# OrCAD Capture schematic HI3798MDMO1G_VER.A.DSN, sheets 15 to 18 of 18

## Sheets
15 SHEET_04: size A3
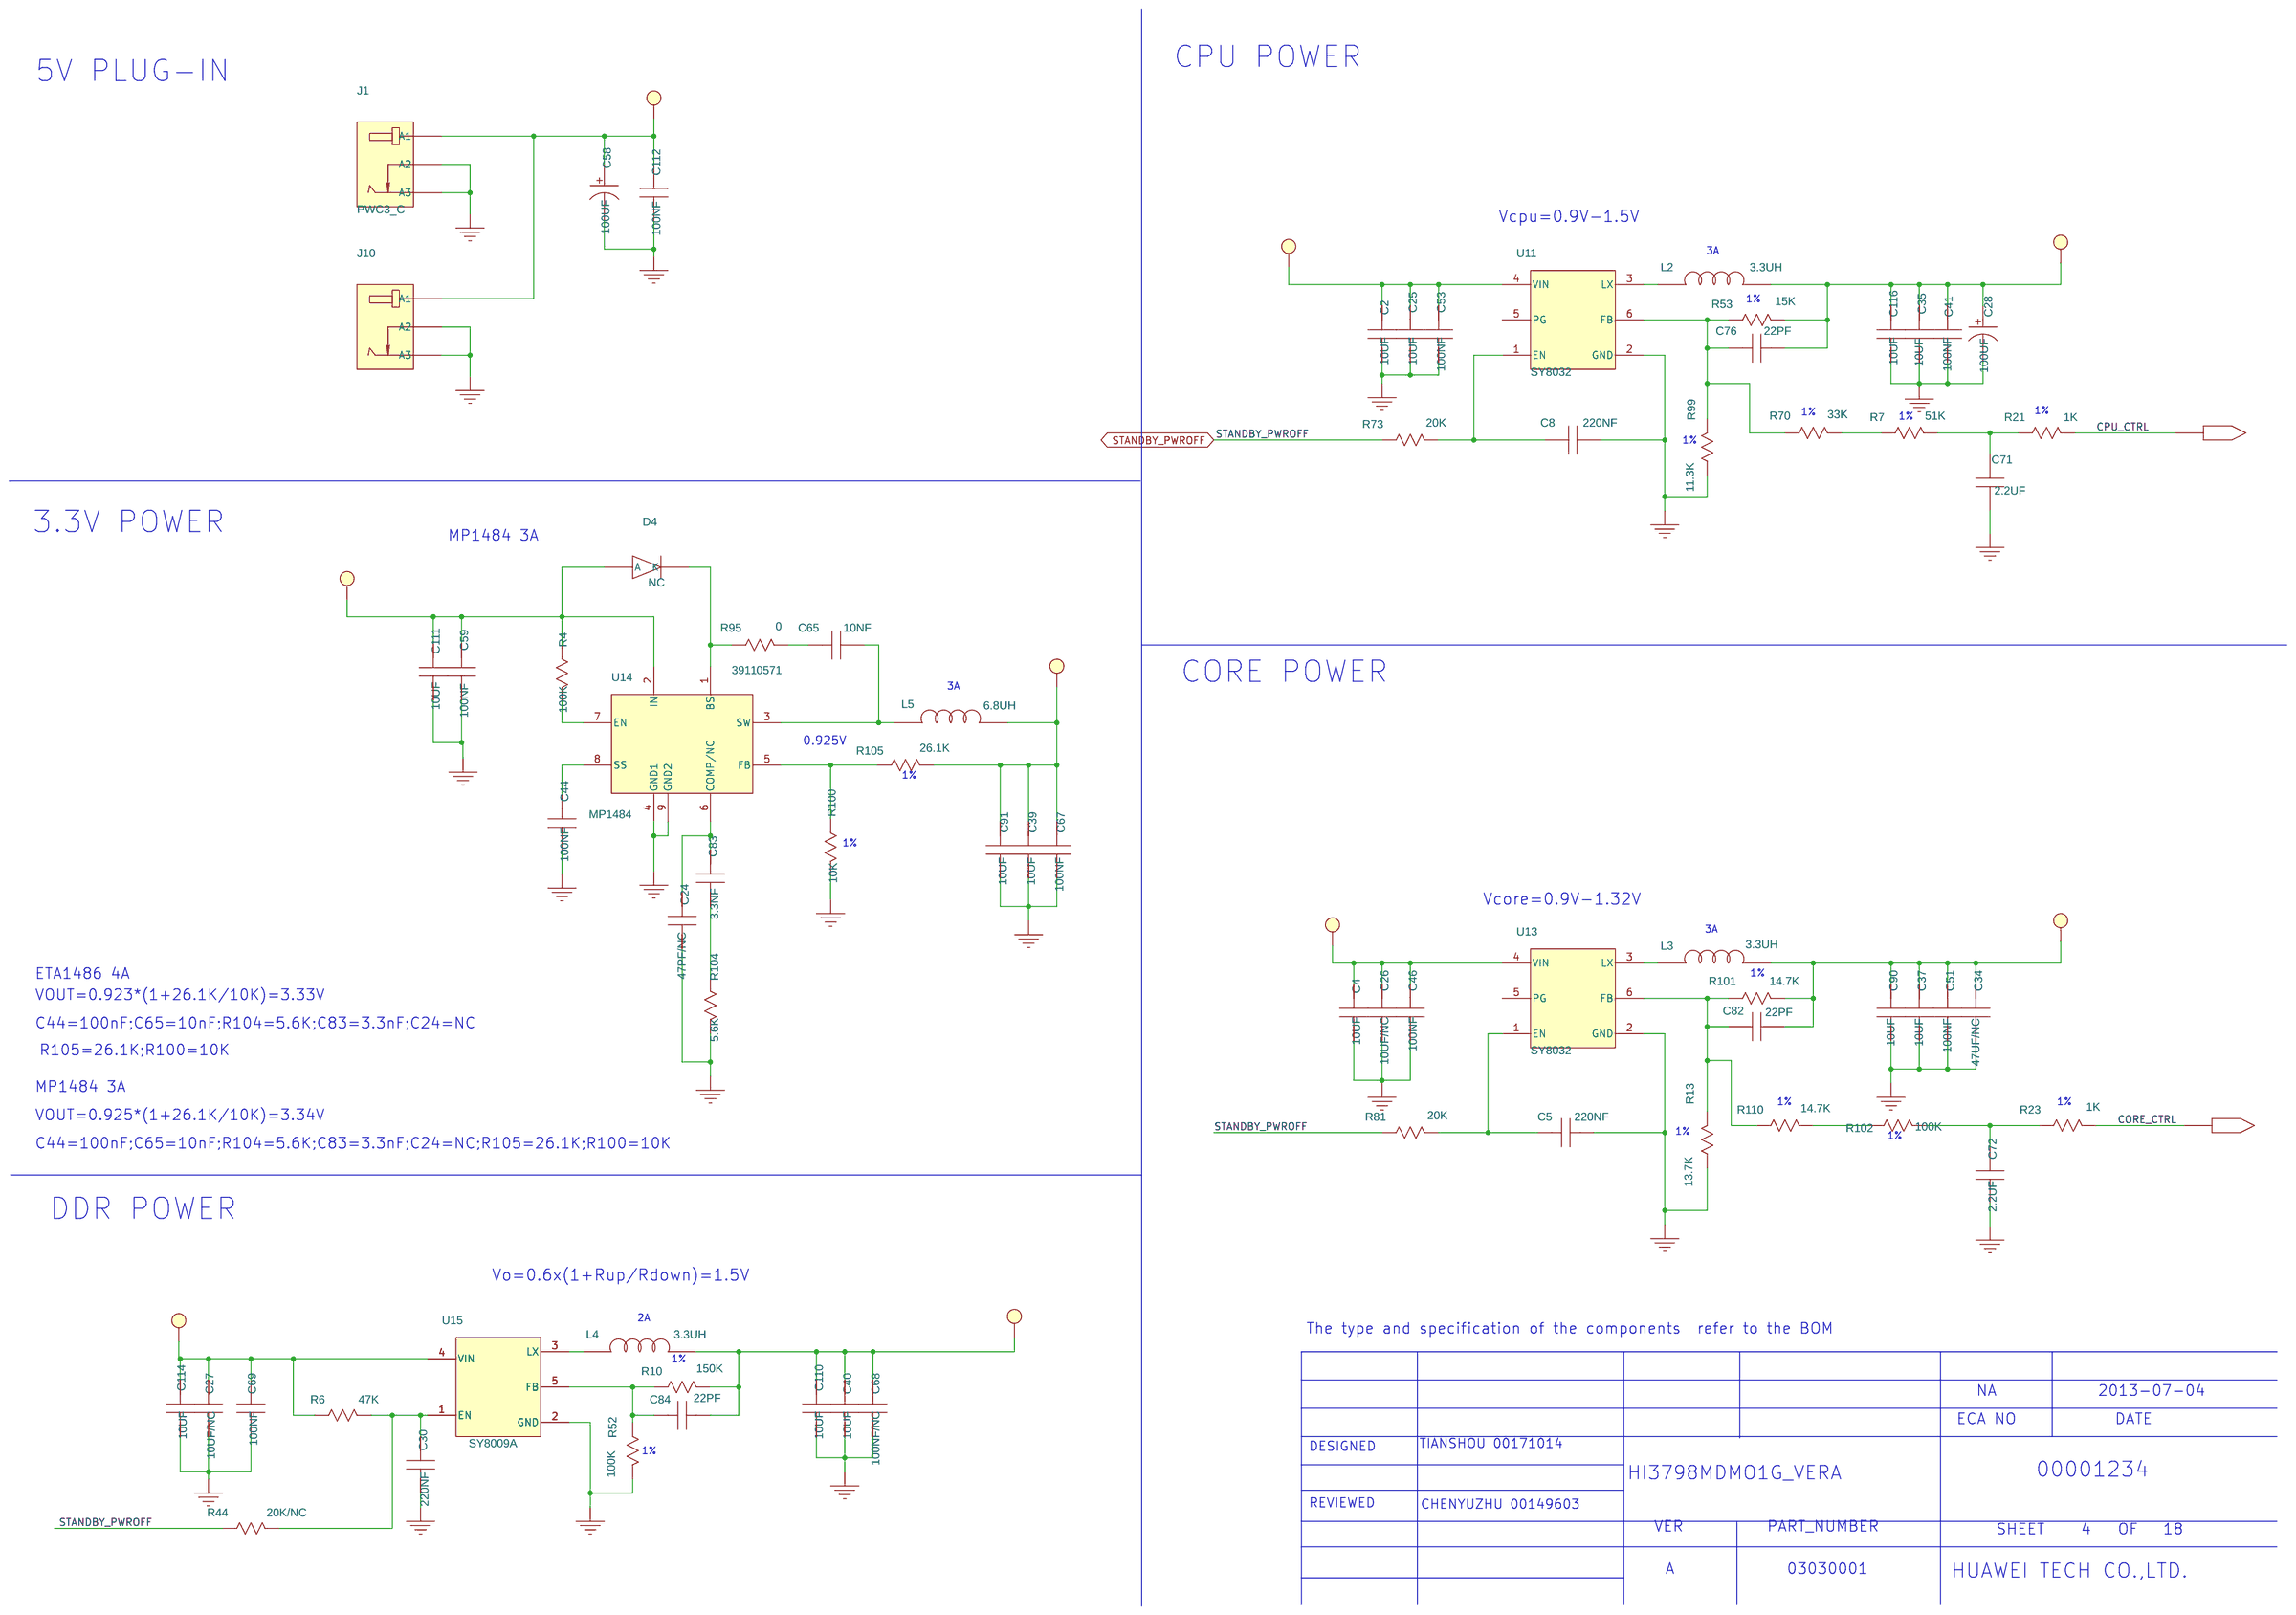
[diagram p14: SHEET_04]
16 SHEET_03: size A3
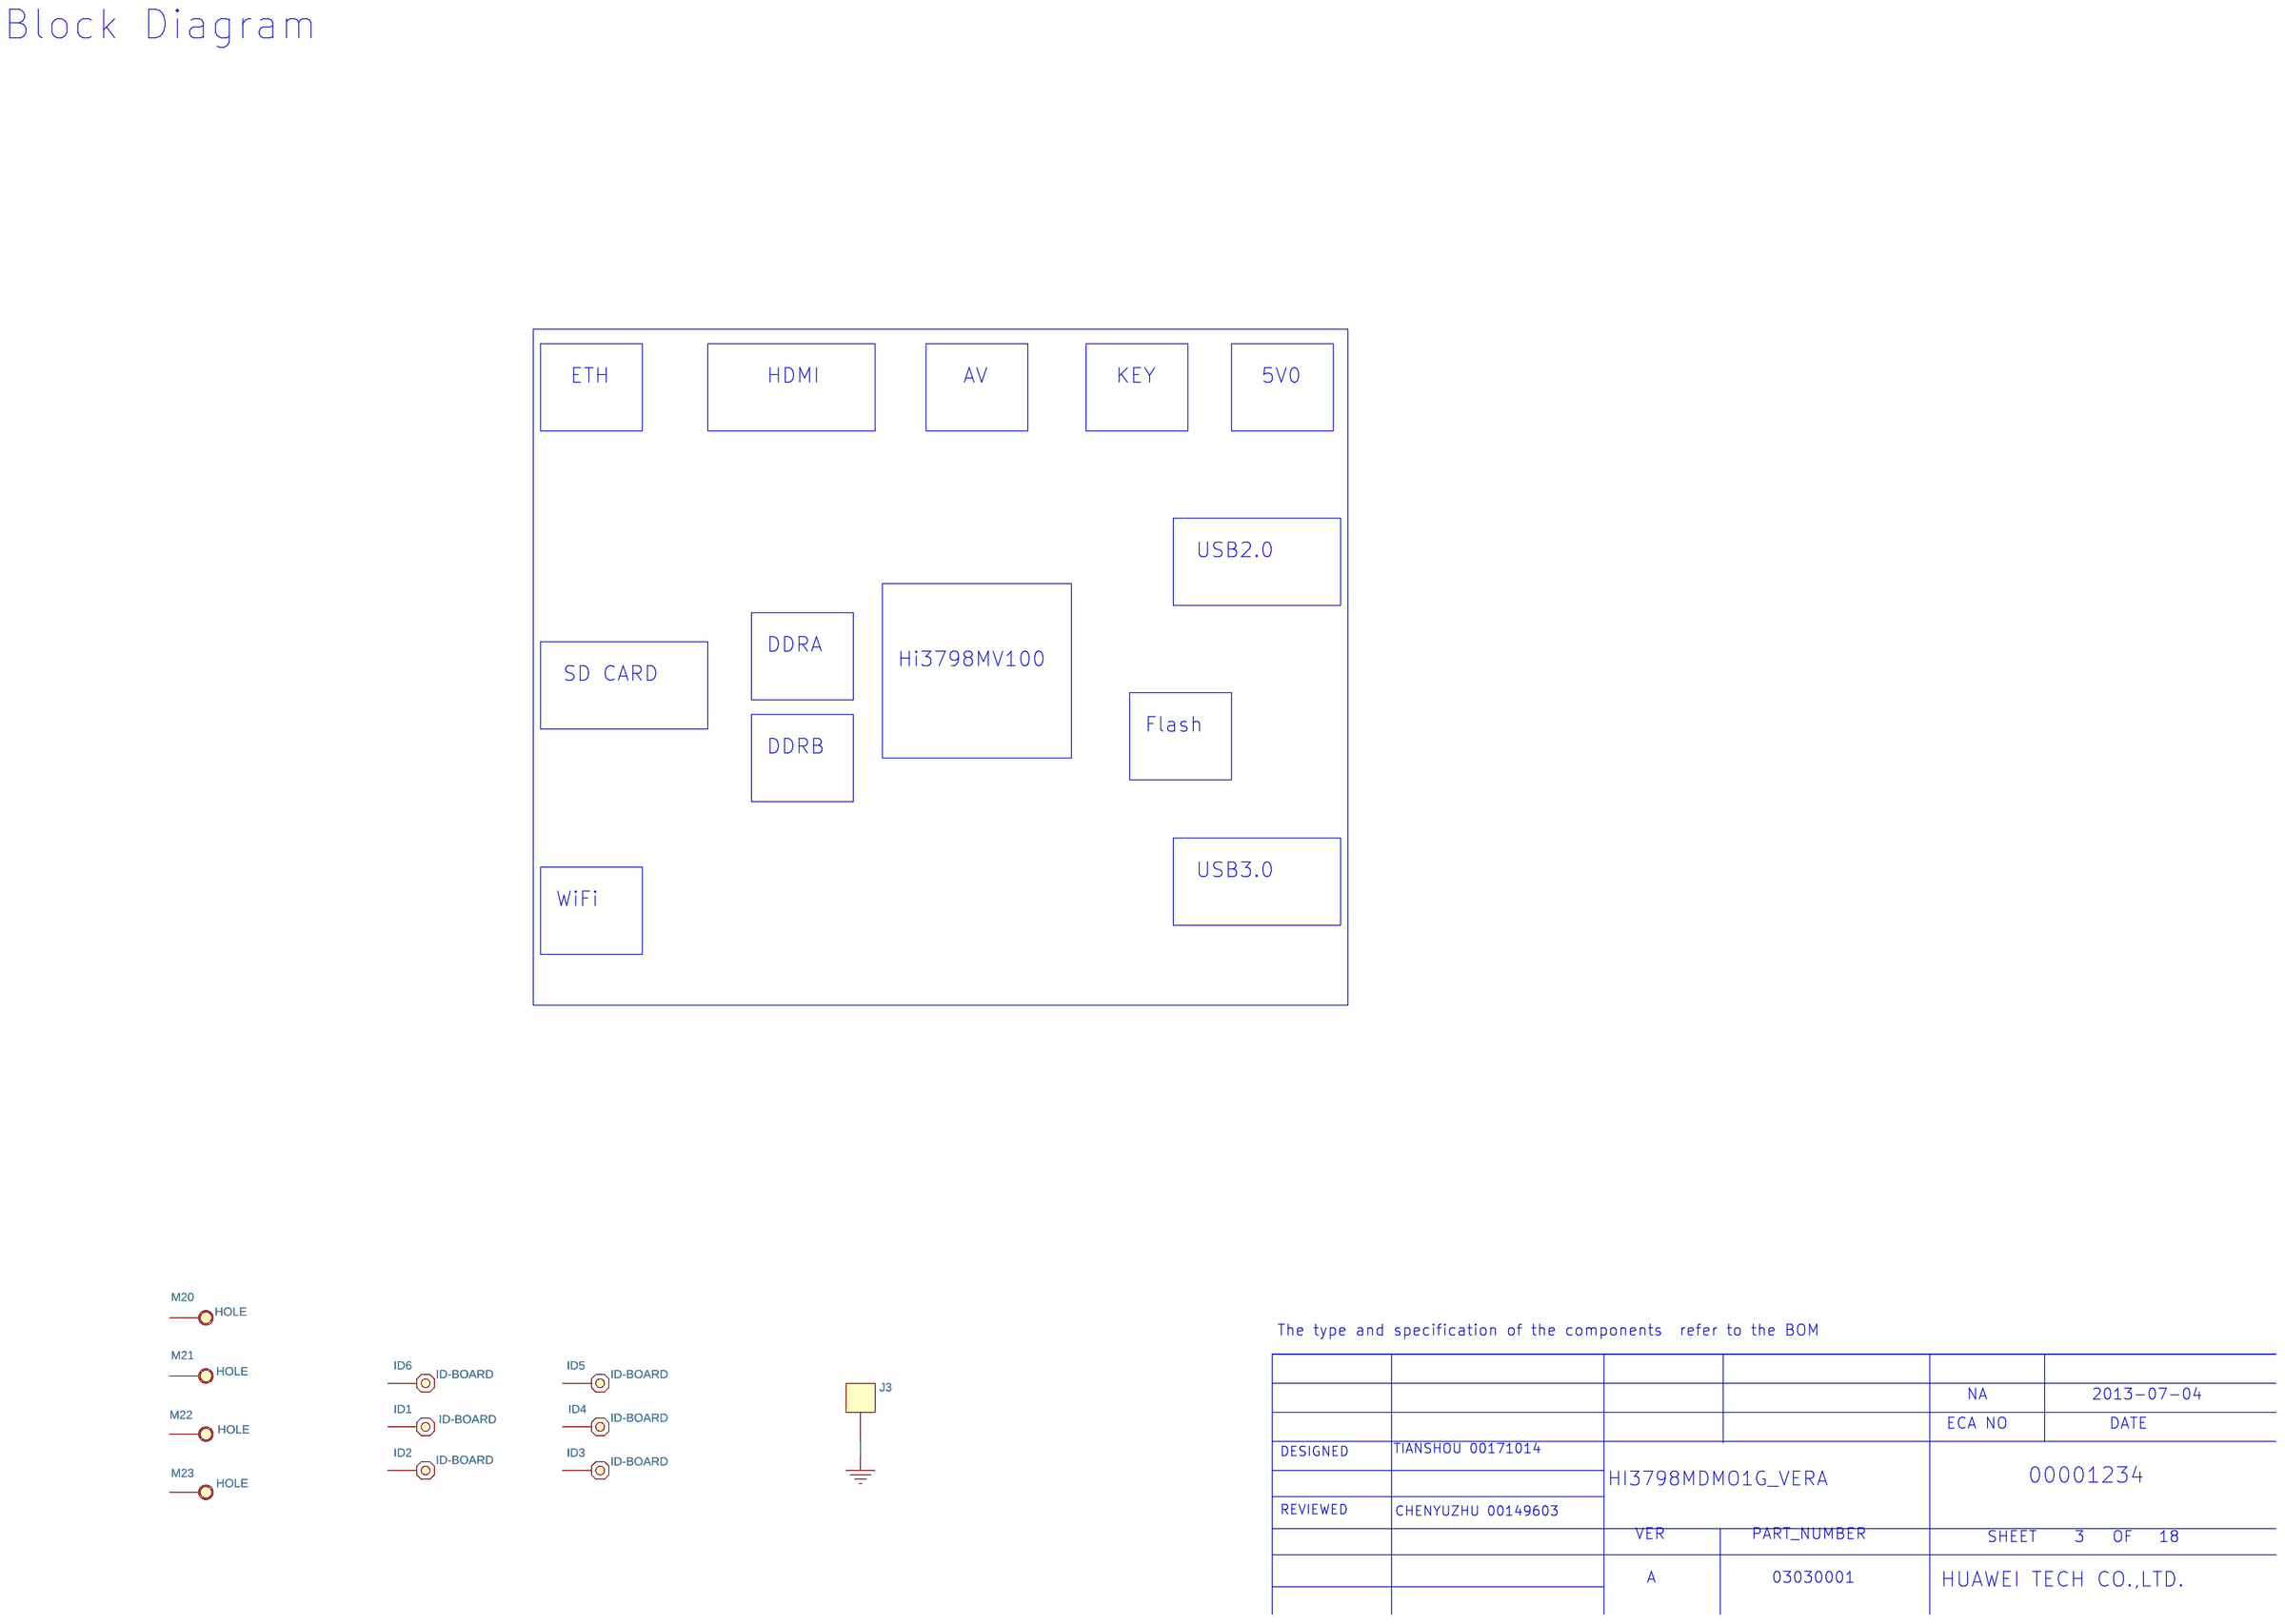
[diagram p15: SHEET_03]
17 SHEET_02
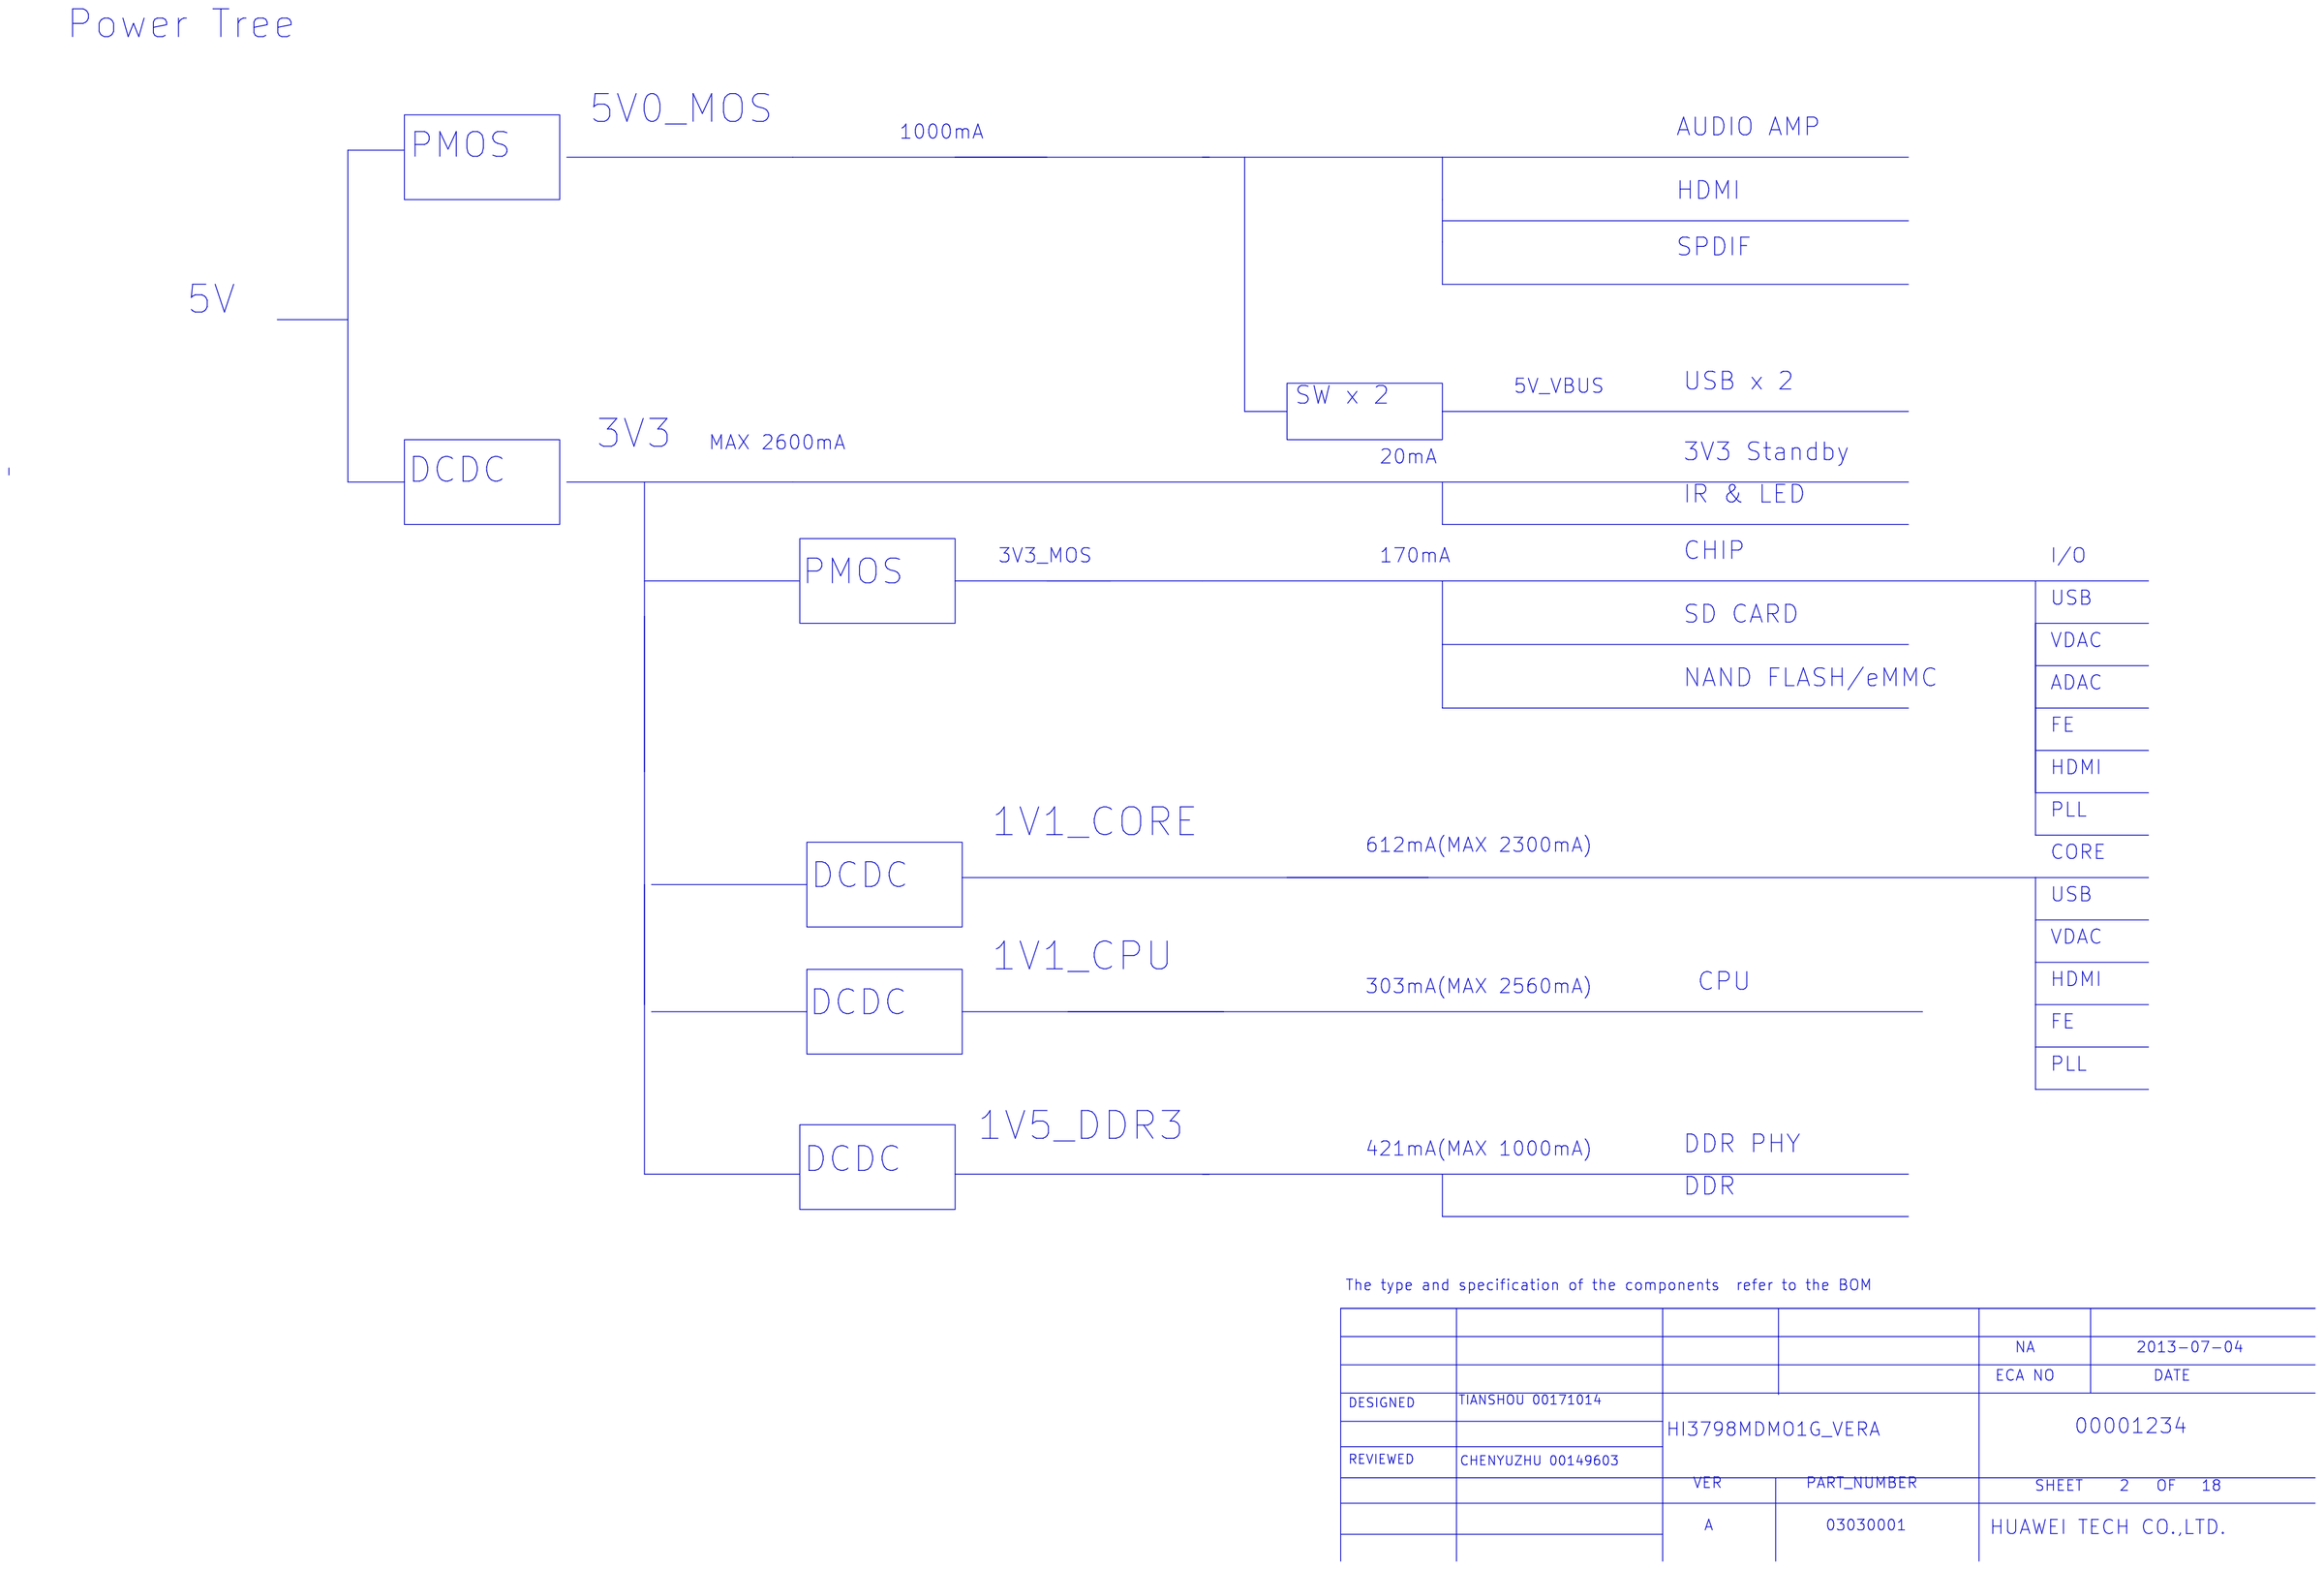
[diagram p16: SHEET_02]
18 SHEET_01
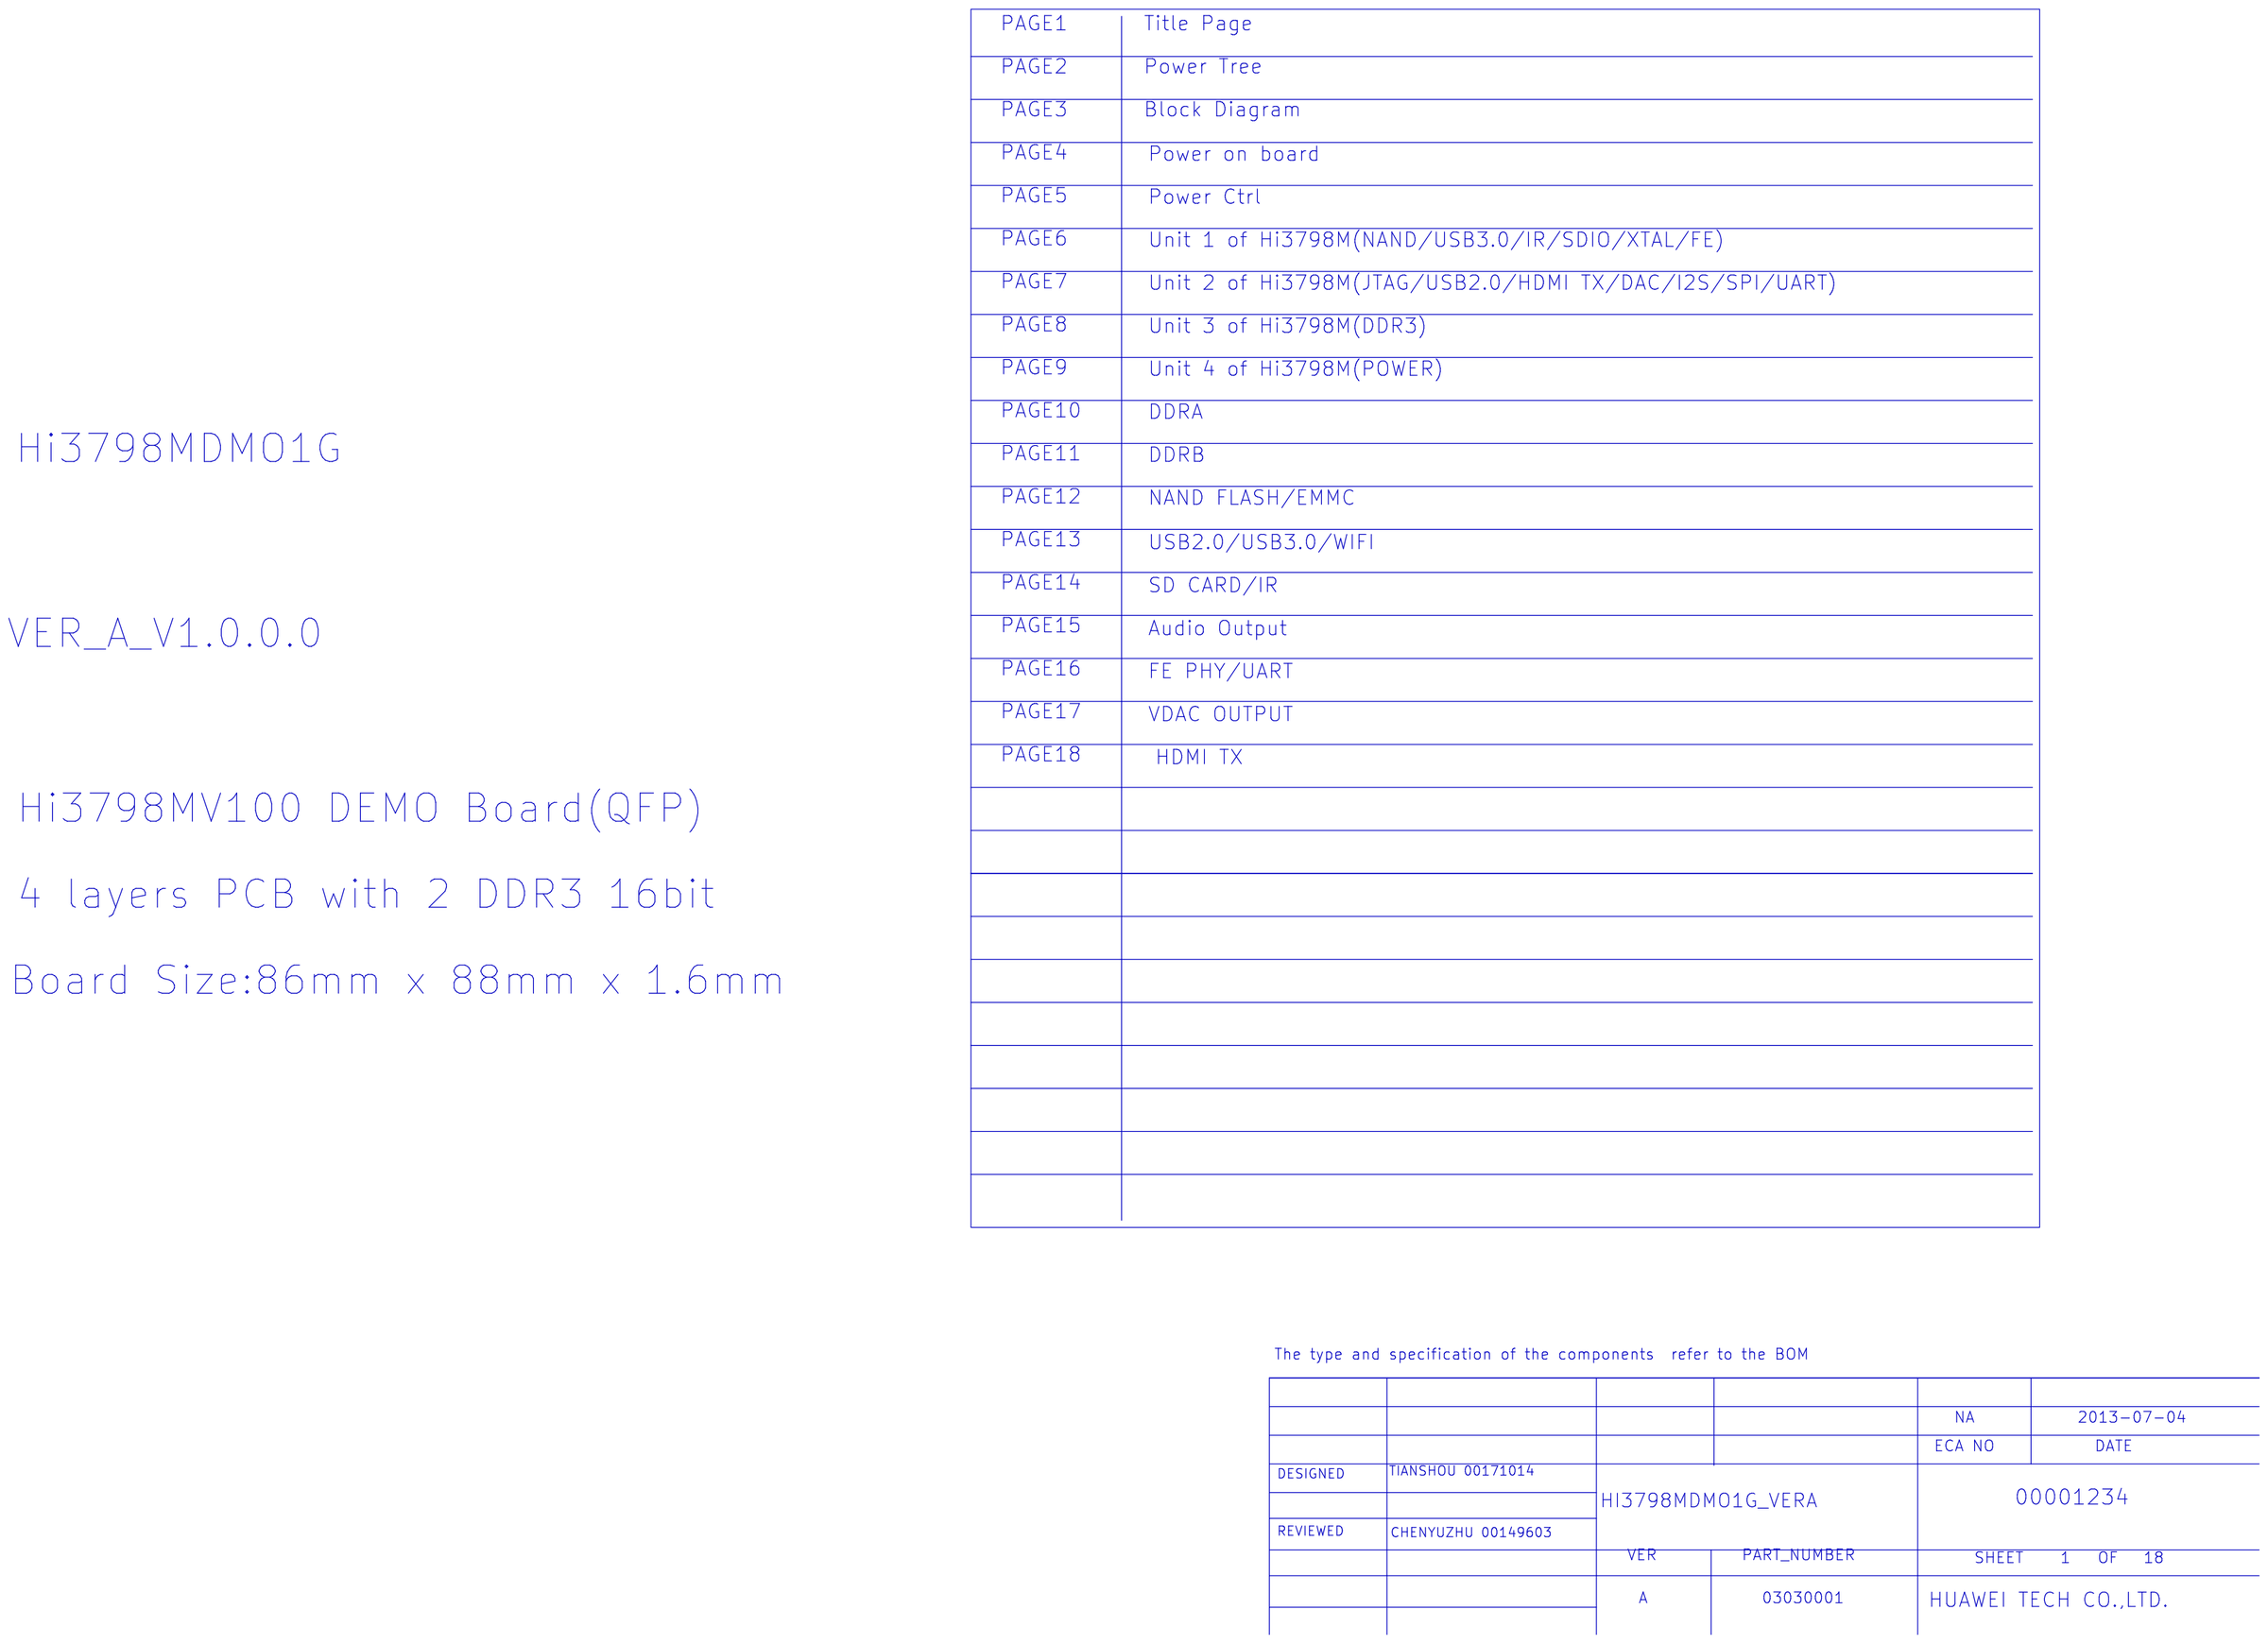
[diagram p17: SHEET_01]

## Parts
sheet SHEET_03
ID1  ID-BOARD  [ID-BOARD]
ID2  ID-BOARD  [ID-BOARD]
ID3  ID-BOARD  [ID-BOARD]
ID4  ID-BOARD  [ID-BOARD]
ID5  ID-BOARD  [ID-BOARD]
ID6  ID-BOARD  [ID-BOARD]
J3  NC  [SIP-1P]
M20  HOLE  [HOLE182-142]
M21  HOLE  [HOLE182-142]
M22  HOLE  [HOLE182-142]
M23  HOLE  [HOLE182-142]
sheet SHEET_04
C2  10UF  [SC0805]
C4  10UF  [SC0805]
C5  220NF  [SC0402]
C8  220NF  [SC0402]
C24  47PF/NC  [SC0402]
C25  10UF  [SC0805]
C26  10UF/NC  [SC0805]
C27  10UF/NC  [SC0805]
C28  100UF  [SAC6666]
C30  220NF  [SC0402]
C34  47UF/NC  [SC1206]
C35  10UF  [SC0603]
C37  10UF  [SC0603]
C39  10UF  [SC0603]
C40  10UF  [SC0603]
C41  100NF  [SC0402]
C44  100NF  [SC0402]
C46  100NF  [SC0402]
C51  100NF  [SC0402]
C53  100NF  [SC0402]
C58  100UF  [SAC6666]
C59  100NF  [SC0402]
C65  10NF  [SC0402]
C67  100NF  [SC0402]
C68  100NF/NC  [SC0402]
C69  100NF  [SC0402]
C71  2.2UF  [HSC0402]
C72  2.2UF  [HSC0402]
C76  22PF  [SC0402]
C82  22PF  [SC0402]
C83  3.3NF  [SC0402]
C84  22PF  [SC0402]
C90  10UF  [SC0603]
C91  10UF  [SC0603]
C110  10UF  [SC0603]
C111  10UF  [SC0805]
C112  100NF  [SC0402]
C114  10UF  [SC0805]
C116  10UF  [SC0603]
D4  NC  [HSOD323A]
J1  PWC3_C  [PWC3-RF-A]
J10  NC  [DC-002]
L2  3.3UH  [SWPA4020S]
L3  3.3UH  [SWPA4020S]
L4  3.3UH  [SWPA4020S]
L5  6.8UH  [SWPA5040S]
R4  100K  [SR0402]
R6  47K  [SR0402]
R7  51K  [SR0402]
R10  150K  [SR0402]
R13  13.7K  [SR0402]
R21  1K  [SR0402]
R23  1K  [SR0402]
R44  20K/NC  [SR0402]
R52  100K  [SR0402]
R53  15K  [SR0402]
R70  33K  [SR0402]
R73  20K  [SR0402]
R81  20K  [SR0402]
R95  0  [SR0402]
R99  11.3K  [SR0402]
R100  10K  [SR0402]
R101  14.7K  [SR0402]
R102  100K  [SR0402]
R104  5.6K  [SR0402]
R105  26.1K  [SR0402]
R110  14.7K  [SR0402]
U11  SY8032  [SOT23_6]
U13  SY8032  [SOT23_6]
U14  MP1484  [SOIC8N]
U15  SY8009A  [SOT23_5]

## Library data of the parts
ID1-ID6 = ID-BOARD: %195%%232%%202%%246%: PCB-MARK点ID-BOARD，亮铜直径40MIL，阻焊开窗直径80MIL，MARK点大小120MIL。; DEVICE: PCB_MARKPOINT_A
J3 = SIP1: %195%%232%%202%%246%: 插针-普通方脚插针-1PIN-单排-直式-5.84MM-2.92MM-2.54MM-THT; %208%%161%%192%%224%%195%%251%%179%%198%: 插针; CODE: 14050101; DEVICE: TSW_101_23_F_S
M20-M23 = HOLE: %195%%232%%202%%246%: 自建封装; DEVICE: M3_HOLE_A
C2 C4 C25-C27 C111 C114 = C: %182%%238%%182%%168%%185%%164%%215%%247%%181%%231%%209%%185%(V): 25; %195%%232%%202%%246%: SMD陶瓷电容-25V-10000NF-+/-20%-X5R-0805; %208%%161%%192%%224%%195%%251%%179%%198%: SMD陶瓷电容; CODE: 8071629; COMPONENT_HIGH_MAX: 1.45MM; DEVICE: C2012X5R1E106KT000N1
C5 C8 C30 = C: %182%%238%%182%%168%%185%%164%%215%%247%%181%%231%%209%%185%(V): 6.3; %195%%232%%202%%246%: SMD陶瓷电容-6.3V-220NF-+/-10%-X5R-0402-BT; %208%%161%%192%%224%%195%%251%%179%%198%: SMD陶瓷电容; CODE: 8070584; COMPONENT_HIGH_MAX: 0.55MM; DEVICE: GRM155R60J224KE01D
C24 = C: %182%%238%%182%%168%%185%%164%%215%%247%%181%%231%%209%%185%(V): 50; %195%%232%%202%%246%: SMD陶瓷电容-50V-0.047NF-±5%-NP0-0402; %208%%161%%192%%224%%195%%251%%179%%198%: SMD陶瓷电容; CODE: 8070549; COMPONENT_HIGH_MAX: 0.55MM; DEVICE: C0402C470J5GAC_7867
C28 C58 = CP: %182%%238%%182%%168%%185%%164%%215%%247%%181%%231%%209%%185%(V): 16; %195%%232%%202%%246%: 非固体SMD铝电容-16V-100UF-+/-20%-6.3*5.4MM-极性-105DEGC-1000H-片式,温度敏感器件-工艺耐温250DEGC,5S; %208%%161%%192%%224%%195%%251%%179%%198%: 非固体SMD铝电容; CODE: 8010269; COMPONENT_HIGH_MAX: 5.7MM; DEVICE: UWT1C101MCL1GB
C34 = C: %182%%238%%182%%168%%185%%164%%215%%247%%181%%231%%209%%185%(V): 6.3; %195%%232%%202%%246%: SMD陶瓷电容-6.3V-47000NF-+/-20%-X5R-1206; %208%%161%%192%%224%%195%%251%%179%%198%: SMD陶瓷电容; CODE: 8070680; COMPONENT_HIGH_MAX: 1.9MM; DEVICE: CM316X5R476M06AT
C35 C37 C39 C40 C90 C91 C110 C116 = C: %182%%238%%182%%168%%185%%164%%215%%247%%181%%231%%209%%185%(V): 6.3; %195%%232%%202%%246%: SMD陶瓷电容-6.3V-10000NF-+/-20%-X5R-0603-BT,TS16949; %208%%161%%192%%224%%195%%251%%179%%198%: SMD陶瓷电容; CODE: 8070649; COMPONENT_HIGH_MAX: 0.9MM; DEVICE: C1608X5R0J106MT0A0E
C41 C44 C46 C51 C53 C59 C67-C69 C112 = C: %182%%238%%182%%168%%185%%164%%215%%247%%181%%231%%209%%185%(V): 16; %195%%232%%202%%246%: SMD陶瓷电容-16V-100NF-±10%-X7R-0402; %208%%161%%192%%224%%195%%251%%179%%198%: SMD陶瓷电容; CODE: 8070614; COMPONENT_HIGH_MAX: 0.6MM; DEVICE: RMEMK105BJ104KV_FR
C65 = C: %182%%238%%182%%168%%185%%164%%215%%247%%181%%231%%209%%185%(V): 16; %195%%232%%202%%246%: SMD陶瓷电容-16V-10NF-+/-10%-X7R-0402-BT,TS16949; %208%%161%%192%%224%%195%%251%%179%%198%: SMD陶瓷电容; CODE: 8070449; COMPONENT_HIGH_MAX: 0.55MM; DEVICE: GRM155R71C103KA01D
C71 C72 = C: %182%%238%%182%%168%%185%%164%%215%%247%%181%%231%%209%%185%(V): 6.3; %195%%232%%202%%246%: SMD陶瓷电容-6.3V-2200NF-+/-20%-X5R-0402-TS16949; %208%%161%%192%%224%%195%%251%%179%%198%: SMD陶瓷电容; CODE: 8070667; COMPONENT_HIGH_MAX: 0.6MM; DEVICE: GRM155R60J225ME15D
C76 C82 C84 = C: %182%%238%%182%%168%%185%%164%%215%%247%%181%%231%%209%%185%(V): 50; %195%%232%%202%%246%: SMD陶瓷电容-50V-0.022NF-+/-5%-NP0-0402-BT; %208%%161%%192%%224%%195%%251%%179%%198%: SMD陶瓷电容; CODE: 8070545; COMPONENT_HIGH_MAX: 0.55MM; DEVICE: RMUMK105CG220JV_F
C83 = C: %182%%238%%182%%168%%185%%164%%215%%247%%181%%231%%209%%185%(V): 50; %195%%232%%202%%246%: SMD陶瓷电容-50V-3.3NF-±10%-X7R-0402; %208%%161%%192%%224%%195%%251%%179%%198%: SMD陶瓷电容; CODE: 8070621; COMPONENT_HIGH_MAX: 0.55MM; DEVICE: GRM155R71H332KA01D
D4 = D_A: %195%%232%%202%%246%: 肖特基二极管-10V-3A-0.24V-SOD323-BT; %208%%161%%192%%224%%195%%251%%179%%198%: 肖特基二极管; CODE: 15010252; COMPONENT_HIGH_MAX: 1.1MM; DEVICE: IN4148
J1 = PWC3_C: %195%%232%%202%%246%: IO连接器-DC JACK-3PIN-母座-3.9/1.3MM弯式-5V2A-00482858; CODE: 14240410; COMPONENT_HIGH_MAX: 11.25MM; DEVICE: DC_012_HW
J10 = PWC3_C: %195%%232%%202%%246%: IO连接器-DC JACK-3PIN-母座-3.9/1.3MM弯式-5V2A-00482858; CODE: *; COMPONENT_HIGH_MAX: 11.25MM; DEVICE: DC_012_HW
L2-L4 = SWPA4020S3R3MT
L5 = SWPA5040S6R8MT
R4 = R: %182%%238%%182%%168%%185%%166%%194%%202%(W): 0.06; %195%%232%%202%%246%: 片式厚膜电阻器-0.0625W-100000OHM-+/-5%-0402; %208%%161%%192%%224%%195%%251%%179%%198%: 片式厚膜电阻器; %215%%232%%214%%181%%212%%202%%208%%237%%198%%171%%178%%238%: +/-5%; CODE: 7090831; COMPONENT_HIGH_MAX: 0.4MM; DEVICE: RK73B1ELTP104J
R6 = R: %182%%238%%182%%168%%185%%166%%194%%202%(W): 0.06; %195%%232%%202%%246%: 片式厚膜电阻器-0.0625W-47000OHM-+/-5%-0402-ELOM; %208%%161%%192%%224%%195%%251%%179%%198%: 片式厚膜电阻器; %215%%232%%214%%181%%212%%202%%208%%237%%198%%171%%178%%238%: +/-5%; CODE: 7090819; COMPONENT_HIGH_MAX: 0.4MM; DEVICE: RC0402JR_0747K
R7 R100 = R: %182%%238%%182%%168%%185%%166%%194%%202%(W): 0.06; %195%%232%%202%%246%: 片式厚膜电阻器-0.0625W-10000OHM-+/-1%-0402-BT; %208%%161%%192%%224%%195%%251%%179%%198%: 片式厚膜电阻器; %215%%232%%214%%181%%212%%202%%208%%237%%198%%171%%178%%238%: +/-1%; CODE: 7090867; COMPONENT_HIGH_MAX: 0.4MM; DEVICE: RK73H1ETTP1002F
R10 = R: %182%%238%%182%%168%%185%%166%%194%%202%(W): 0.06; %195%%232%%202%%246%: 片式厚膜电阻器-0.0625W-150000OHM-+/-1%-0402; %208%%161%%192%%224%%195%%251%%179%%198%: 片式厚膜电阻器; %215%%232%%214%%181%%212%%202%%208%%237%%198%%171%%178%%238%: +/-1%; CODE: 7090833; COMPONENT_HIGH_MAX: 0.4MM; DEVICE: RK73H1ELTP1503F
R13 = R: %182%%238%%182%%168%%185%%166%%194%%202%(W): 0.06; %195%%232%%202%%246%: 片式厚膜电阻器-0.0625W-13700OHM-+/- 1%-0402-供电专用-供电专用; %208%%161%%192%%224%%195%%251%%179%%198%: 片式厚膜电阻器; %215%%232%%214%%181%%212%%202%%208%%237%%198%%171%%178%%238%: +/- 1%; CODE: 7091435; COMPONENT_HIGH_MAX: 0.4MM; DEVICE: RC0402FR_0713K7L
R21 R23 = R: %182%%238%%182%%168%%185%%166%%194%%202%(W): 0.1; %195%%232%%202%%246%: 片式厚膜电阻器-0.1W-1000OHM-+/-1%-0603; %208%%161%%192%%224%%195%%251%%179%%198%: 片式厚膜电阻器; %215%%232%%214%%181%%212%%202%%208%%237%%198%%171%%178%%238%: +/-1%; CODE: 7092250; COMPONENT_HIGH_MAX: 0.5MM; DEVICE: RK73H1JTTD1001F
R44 R73 R81 = R: %182%%238%%182%%168%%185%%166%%194%%202%(W): 0.06; %195%%232%%202%%246%: 片式厚膜电阻器-0.0625W-20000OHM-+/-1%-0402-TS16949; %208%%161%%192%%224%%195%%251%%179%%198%: 片式厚膜电阻器; %215%%232%%214%%181%%212%%202%%208%%237%%198%%171%%178%%238%: +/-1%; CODE: 7091374; COMPONENT_HIGH_MAX: 0.4MM; DEVICE: RC_02W2002FT
R52 = R: %182%%238%%182%%168%%185%%166%%194%%202%(W): 0.06; %195%%232%%202%%246%: 片式厚膜电阻器-0.0625W-100000OHM-+/-5%-0402-BT; %208%%161%%192%%224%%195%%251%%179%%198%: 片式厚膜电阻器; %215%%232%%214%%181%%212%%202%%208%%237%%198%%171%%178%%238%: +/-5%; CODE: 7090831; COMPONENT_HIGH_MAX: 0.4MM; DEVICE: RK73B1ELTP104J
R53 = R: %182%%238%%182%%168%%185%%166%%194%%202%(W): 0.06; %195%%232%%202%%246%: 片式厚膜电阻器-0.0625W-13000OHM-+/-1%-0402-BT; %208%%161%%192%%224%%195%%251%%179%%198%: 片式厚膜电阻器; %215%%232%%214%%181%%212%%202%%208%%237%%198%%171%%178%%238%: +/-1%; CODE: *; COMPONENT_HIGH_MAX: 0.4MM; DEVICE: RC_02W1502FT
R70 = R: %182%%238%%182%%168%%185%%166%%194%%202%(W): 0.06; %195%%232%%202%%246%: 片式厚膜电阻器-0.0625W-75000OHM-+/-1%-0402; %208%%161%%192%%224%%195%%251%%179%%198%: 片式厚膜电阻器; %215%%232%%214%%181%%212%%202%%208%%237%%198%%171%%178%%238%: +/-1%; CODE: 7091008; COMPONENT_HIGH_MAX: 0.4MM; DEVICE: RK73H1ETTD7502F
R95 = R: %182%%238%%182%%168%%185%%166%%194%%202%(W): 0.06; %195%%232%%202%%246%: 片式厚膜电阻器-0.0625W-0OHM-< 50MOHM-0402-1A-BT; %208%%161%%192%%224%%195%%251%%179%%198%: 片式厚膜电阻器; %215%%232%%214%%181%%212%%202%%208%%237%%198%%171%%178%%238%: < 50MOHM; CODE: 7090800; DEVICE: RC0402JR_070R
R99 = R: %182%%238%%182%%168%%185%%166%%194%%202%(W): 0.06; %195%%232%%202%%246%: 片式厚膜电阻器-0.0625W-11000OHM-+/-1%-0402-BT; %208%%161%%192%%224%%195%%251%%179%%198%: 片式厚膜电阻器; %215%%232%%214%%181%%212%%202%%208%%237%%198%%171%%178%%238%: +/-1%; CODE: 7091271; COMPONENT_HIGH_MAX: 0.4MM; DEVICE: RK73H1ETTP1102F
R101 R110 = R: %182%%238%%182%%168%%185%%166%%194%%202%(W): 0.06; %195%%232%%202%%246%: 片式厚膜电阻器-0.0625W-14700OHM-+/-1%-0402; %208%%161%%192%%224%%195%%251%%179%%198%: 片式厚膜电阻器; %215%%232%%214%%181%%212%%202%%208%%237%%198%%171%%178%%238%: +/-1%; CODE: *; COMPONENT_HIGH_MAX: 0.4MM; DEVICE: RK73H1ETTD7502F
R102 = R: %182%%238%%182%%168%%185%%166%%194%%202%(W): 0.06; %195%%232%%202%%246%: 片式厚膜电阻器-0.0625W-100000OHM-+/-1%-0402; %208%%161%%192%%224%%195%%251%%179%%198%: 片式厚膜电阻器; %215%%232%%214%%181%%212%%202%%208%%237%%198%%171%%178%%238%: +/-1%; CODE: 7090875; COMPONENT_HIGH_MAX: 0.4MM; DEVICE: RK73H1ETTP1003F
R104 = R: %182%%238%%182%%168%%185%%166%%194%%202%(W): 0.06; %195%%232%%202%%246%: 片式厚膜电阻器-0.0625W-5600OHM-+/-1%-0402-BT; %208%%161%%192%%224%%195%%251%%179%%198%: 片式厚膜电阻器; %215%%232%%214%%181%%212%%202%%208%%237%%198%%171%%178%%238%: +/-1%; CODE: 7091275; COMPONENT_HIGH_MAX: 0.4MM; DEVICE: RK73H1ETTP5601F
R105 = R: %182%%238%%182%%168%%185%%166%%194%%202%(W): 0.06; %195%%232%%202%%246%: 片式厚膜电阻器-0.0625W-26100OHM-+/-1%-0402; %208%%161%%192%%224%%195%%251%%179%%198%: 片式厚膜电阻器; %215%%232%%214%%181%%212%%202%%208%%237%%198%%171%%178%%238%: +/-5%; CODE: *; COMPONENT_HIGH_MAX: 0.4MM; DEVICE: RK73B1ETTP273J
U11 U13 = SY8032
U14 = MP1484: CODE: 39110571
U15 = SY8009A

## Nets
1V1_CORE: C34.1(A) C37.1(A) C51.1(A) C82.2(B) C90.1(A) L3.2(B) R101.2(B) ; also on sheet 10 12 13
1V1_CPU: C28.1 C35.1(A) C41.1(A) C76.2(B) C116.1(A) L2.2(B) R53.2(B) ; also on sheet 10
1V5_DDR3: C40.1(A) C68.1(A) C84.2(B) C110.1(A) L4.2(B) R10.2(B) ; also on sheet 8 9 11
3V3: C2.1(A) C4.1(A) C25.1(A) C26.1(A) C27.1(A) C39.1(A) C46.1(A) C53.1(A) C67.1(A) C69.1(A) C91.1(A) C114.1(A) L5.2(B) R6.1(A) R105.2(B) U11.4(VIN) U13.4(VIN) U15.4(VIN) ; also on sheet 3 5 10 13 14
5V0: C58.1 C59.1(A) C111.1(A) C112.1(A) D4.2(A) J1.1(A1) J10.1(A1) R4.1(A) U14.2(IN) ; also on sheet 14
GND: C2.2(B) C4.2(B) C5.2(B) C8.2(B) C24.2(B) C25.2(B) C26.2(B) C27.2(B) C28.2 C30.2(B) C34.2(B) C35.2(B) C37.2(B) C39.2(B) C40.2(B) C41.2(B) C44.2(B) C46.2(B) C51.2(B) C53.2(B) C58.2 C59.2(B) C67.2(B) C68.2(B) C69.2(B) C71.2(B) C72.2(B) C90.2(B) C91.2(B) C110.2(B) C111.2(B) C112.2(B) C114.2(B) C116.2(B) J1.2(A2) J1.3(A3) J3.1 J10.2(A2) J10.3(A3) R13.1(A) R52.2(B) R99.1(A) R100.2(B) R104.2(B) U11.2(GND) U13.2(GND) U14.4(GND1) U14.9(GND2) U15.2(GND) ; also on sheet 1 2 3 4 5 6 7 8 9 10 11 12 13 14
CORE_CTRL: R23.2(B) ; also on sheet 12
CPU_CTRL: R21.2(B) ; also on sheet 12
STANDBY_PWROFF: R44.1(A) R73.1(A) R81.1(A) ; also on sheet 13 14
N3785646: C71.1(A) R7.2(B) R21.1(A)
N3786188: C82.1(A) R13.2(B) R101.1(A) R110.1(A) U13.6(FB)
N3786224: C5.1(A) R81.2(B) U13.1(EN)
N3786240: C65.2(B) L5.1(A) U14.3(SW)
N3786256: C44.1(A) U14.8(SS)
N3786340: C76.1(A) R53.1(A) R70.1(A) R99.2(B) U11.6(FB)
N3786376: C8.1(A) R73.2(B) U11.1(EN)
N3786392: L4.1(A) U15.3(LX)
N3786396: C84.1(A) R10.1(A) R52.1(A) U15.5(FB)
N3786468: L3.1(A) U13.3(LX)
N3786472: R102.1(A) R110.2(B)
N3786476: L2.1(A) U11.3(LX)
N3786480: C65.1(A) R95.2(B)
N3786484: R4.2(B) U14.7(EN)
N3786492: C24.1(A) C83.1(A) U14.6(COMP/NC)
N3786508: C83.2(B) R104.1(A)
N3786512: D4.1(K) R95.1(A) U14.1(BS)
N3786528: R100.1(A) R105.1(A) U14.5(FB)
N3786600: C30.1(A) R6.2(B) R44.2(B) U15.1(EN)
N3786684: C72.1(A) R23.1(A) R102.2(B)
N3786696: R7.1(A) R70.2(B)

Not connected (* = marked no-connect by the designer): ID1 1; ID2 1; ID3 1; ID4 1; ID5 1; ID6 1; M20 1(GND); M21 1(GND); M22 1(GND); M23 1(GND); U11 5(PG); U13 5(PG)

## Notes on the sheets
sheet 15
- CPU POWER
- 5V PLUG-IN
- Vcpu=0.9V-1.5V
- 3A
- 1%
- 1%
- 1%
- 1%
- 1%
- 3.3V POWER
- MP1484 3A
- CORE POWER
- 3A
- 0.925V
- 1%
- 1%
- Vcore=0.9V-1.32V
- 3A
- ETA1486 4A
- 1%
- VOUT=0.923*(1+26.1K/10K)=3.33V
- C44=100nF;C65=10nF;R104=5.6K;C83=3.3nF;C24=NC
- R105=26.1K;R100=10K
- MP1484 3A
- 1%
- 1%
- VOUT=0.925*(1+26.1K/10K)=3.34V
- 1%
- 1%
- C44=100nF;C65=10nF;R104=5.6K;C83=3.3nF;C24=NC;R105=26.1K;R100=10K
- DDR POWER
- Vo=0.6x(1+Rup/Rdown)=1.5V
- 2A
- The type and specification of the components  refer to the BOM
- 1%
- NA
- 2013-07-04
- ECA NO
- DATE
- 1%
- DESIGNED
- TIANSHOU 00171014
- HI3798MDMO1G_VERA
- 00001234
- REVIEWED
- CHENYUZHU 00149603
- VER
- PART_NUMBER
- SHEET
- 4
- OF
- 18
- A
- 03030001
- HUAWEI TECH CO.,LTD.
sheet 16
- Block Diagram
- ETH
- HDMI
- AV
- KEY
- 5V0
- USB2.0
- DDRA
- Hi3798MV100
- SD CARD
- Flash
- DDRB
- USB3.0
- WiFi
- The type and specification of the components  refer to the BOM
- NA
- 2013-07-04
- ECA NO
- DATE
- DESIGNED
- TIANSHOU 00171014
- 00001234
- HI3798MDMO1G_VERA
- REVIEWED
- CHENYUZHU 00149603
- VER
- PART_NUMBER
- SHEET
- 3
- OF
- 18
- A
- 03030001
- HUAWEI TECH CO.,LTD.
sheet 17
- Power Tree
- 5V0_MOS
- PMOS
- 1000mA
- AUDIO AMP
- HDMI
- SPDIF
- 5V
- 5V_VBUS
- USB x 2
- SW x 2
- 3V3
- MAX 2600mA
- 20mA
- 3V3 Standby
- DCDC
- IR & LED
- 3V3_MOS
- 170mA
- CHIP
- I/O
- PMOS
- USB
- SD CARD
- VDAC
- NAND FLASH/eMMC
- ADAC
- FE
- HDMI
- 1V1_CORE
- PLL
- 612mA(MAX 2300mA)
- CORE
- DCDC
- USB
- VDAC
- 1V1_CPU
- 303mA(MAX 2560mA)
- CPU
- HDMI
- DCDC
- FE
- PLL
- 1V5_DDR3
- DCDC
- 421mA(MAX 1000mA)
- DDR PHY
- DDR
- The type and specification of the components  refer to the BOM
- NA
- 2013-07-04
- ECA NO
- DATE
- DESIGNED
- TIANSHOU 00171014
- HI3798MDMO1G_VERA
- 00001234
- REVIEWED
- CHENYUZHU 00149603
- VER
- PART_NUMBER
- SHEET
- 2
- OF
- 18
- A
- 03030001
- HUAWEI TECH CO.,LTD.
sheet 18
- PAGE1
- Title Page
- PAGE2
- Power Tree
- PAGE3
- Block Diagram
- PAGE4
- Power on board
- PAGE5
- Power Ctrl
- PAGE6
- Unit 1 of Hi3798M(NAND/USB3.0/IR/SDIO/XTAL/FE)
- PAGE7
- Unit 2 of Hi3798M(JTAG/USB2.0/HDMI TX/DAC/I2S/SPI/UART)
- PAGE8
- Unit 3 of Hi3798M(DDR3)
- PAGE9
- Unit 4 of Hi3798M(POWER)
- PAGE10
- DDRA
- Hi3798MDMO1G
- PAGE11
- DDRB
- PAGE12
- NAND FLASH/EMMC
- PAGE13
- USB2.0/USB3.0/WIFI
- PAGE14
- SD CARD/IR
- VER_A_V1.0.0.0
- PAGE15
- Audio Output
- PAGE16
- FE PHY/UART
- PAGE17
- VDAC OUTPUT
- PAGE18
- HDMI TX
- Hi3798MV100 DEMO Board(QFP)
- 4 layers PCB with 2 DDR3 16bit
- Board Size:86mm x 88mm x 1.6mm
- The type and specification of the components  refer to the BOM
- NA
- 2013-07-04
- ECA NO
- DATE
- DESIGNED
- TIANSHOU 00171014
- HI3798MDMO1G_VERA
- 00001234
- REVIEWED
- CHENYUZHU 00149603
- VER
- PART_NUMBER
- SHEET
- 1
- OF
- 18
- A
- 03030001
- HUAWEI TECH CO.,LTD.
